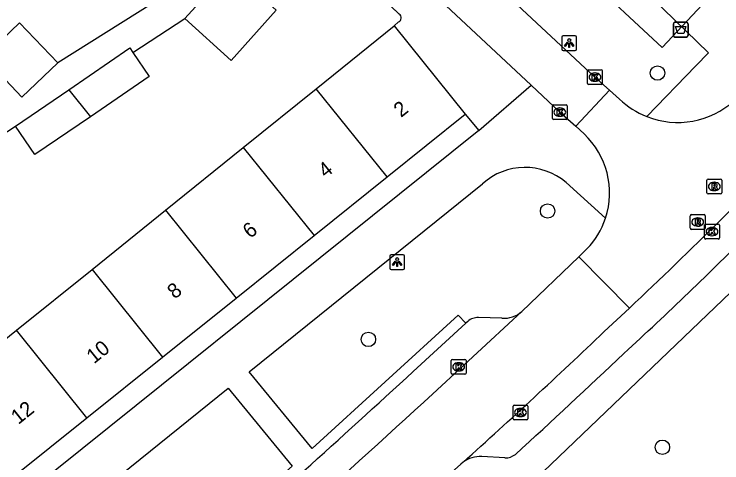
# Model space of a CAD drawing. Extents: x 162347 to 162868, y 381221 to 381813.
# Drawn here: x 162598.22 to 162646.11, y 381599.97 to 381630.34 of the extents above; entities that cross this region are included whole.
import ezdxf

# ---------------------------------------------------------------- set-up
doc = ezdxf.new("R2010")
doc.units = 0
for name, color, linetype in [('IMGEO_Afvalbak', 7, 'Continuous'), ('IMGEO_Boom', 7, 'Continuous'), ('IMGEO_Hek', 7, 'Continuous'), ('IMGEO_Kolk', 7, 'Continuous'), ('IMGEO_Lichtpunt', 7, 'Continuous'), ('IMGEO_Muur', 7, 'Continuous'), ('IMGEO_Pand', 7, 'Continuous'), ('IMGEO_Pand_nummerreeks', 7, 'Continuous'), ('IMGEO_Parkeervlak_open', 7, 'Continuous'), ('IMGEO_Rijbaan_lokaal_open', 7, 'Continuous'), ('IMGEO_Rioolput', 7, 'Continuous'), ('IMGEO_Voetpad_open', 7, 'Continuous')]:
    doc.layers.add(name, color=color, linetype=linetype)

msp = doc.modelspace()

# ---------------------------------------------------------------- linework, layer by layer
at = {"layer": 'IMGEO_Afvalbak'}
for p, q in [((162642.832, 381628.889), (162642.832, 381629.689)), ((162642.832, 381629.689), (162642.832, 381628.889)), ((162642.932, 381629.789), (162643.722, 381629.789)), ((162643.722, 381629.789), (162642.932, 381629.789)), ((162643.822, 381629.689), (162643.822, 381628.889)), ((162643.822, 381628.889), (162643.822, 381629.689)), ((162643.722, 381628.789), (162642.932, 381628.789)), ((162642.932, 381628.789), (162643.722, 381628.789))]:
    msp.add_line(p, q, dxfattribs=at)
msp.add_lwpolyline([(162642.975, 381629.503), (162643.679, 381629.503), (162643.53, 381629.033), (162643.124, 381629.033), (162642.975, 381629.503)], dxfattribs=at)
for centre, start, end in [((162642.932, 381629.689), 90, 180), ((162642.932, 381629.689), 90, 180), ((162643.722, 381629.689), 0, 90), ((162643.722, 381629.689), 360, 90), ((162642.932, 381628.889), 180, 270), ((162642.932, 381628.889), 180, 270), ((162643.722, 381628.889), 270, 0), ((162643.722, 381628.889), 270, 0)]:
    msp.add_arc(centre, 0.1, start, end, dxfattribs=at)
at = {"layer": 'IMGEO_Boom'}
for centre in [(162641.754, 381626.354), (162634.319, 381617.015), (162622.19, 381608.325), (162642.088, 381601.02)]:
    msp.add_circle(centre, 0.489, dxfattribs=at)
at = {"layer": 'IMGEO_Hek'}
msp.add_lwpolyline([(162652.232, 381638.954), (162642.062, 381628.072), (162636.69, 381633.102)], dxfattribs=at)
at = {"layer": 'IMGEO_Kolk'}
for p, q in [((162637.021, 381625.651), (162637.021, 381626.503)), ((162637.096, 381626.577), (162637.948, 381626.577)), ((162637.509, 381626.357), (162637.534, 381626.357)), ((162638.022, 381626.503), (162638.022, 381625.651)), ((162637.532, 381625.797), (162637.507, 381625.797)), ((162637.948, 381625.577), (162637.096, 381625.577)), ((162634.644, 381623.282), (162634.644, 381624.134)), ((162634.719, 381624.208), (162635.571, 381624.208)), ((162635.132, 381623.988), (162635.157, 381623.988)), ((162635.645, 381624.134), (162635.645, 381623.282)), ((162635.155, 381623.428), (162635.13, 381623.428)), ((162635.571, 381623.208), (162634.719, 381623.208)), ((162645.016, 381616.12), (162645.868, 381616.12)), ((162644.941, 381615.194), (162644.941, 381616.046)), ((162645.429, 381615.9), (162645.454, 381615.9)), ((162645.942, 381616.046), (162645.942, 381615.194)), ((162645.452, 381615.34), (162645.427, 381615.34)), ((162645.868, 381615.12), (162645.016, 381615.12)), ((162627.802, 381606.041), (162627.802, 381606.893)), ((162627.877, 381606.967), (162628.729, 381606.967)), ((162628.29, 381606.747), (162628.315, 381606.747)), ((162628.803, 381606.893), (162628.803, 381606.041)), ((162628.313, 381606.187), (162628.288, 381606.187)), ((162628.729, 381605.967), (162627.877, 381605.967)), ((162631.982, 381602.949), (162631.982, 381603.801)), ((162632.057, 381603.875), (162632.909, 381603.875)), ((162632.47, 381603.655), (162632.495, 381603.655)), ((162632.983, 381603.801), (162632.983, 381602.949)), ((162632.909, 381602.875), (162632.057, 381602.875)), ((162632.493, 381603.095), (162632.468, 381603.095))]:
    msp.add_line(p, q, dxfattribs=at)
for points in [[(162637.021, 381625.651), (162637.021, 381626.503)], [(162637.096, 381626.577), (162637.948, 381626.577)], [(162637.342, 381626.277), (162637.465, 381626.277), (162637.465, 381626.126), (162637.595, 381626.277), (162637.759, 381626.277), (162637.613, 381626.126), (162637.766, 381625.877), (162637.614, 381625.877), (162637.529, 381626.041), (162637.465, 381625.974), (162637.465, 381625.877), (162637.342, 381625.877), (162637.342, 381626.277)], [(162638.022, 381626.503), (162638.022, 381625.651)], [(162637.948, 381625.577), (162637.096, 381625.577)], [(162634.644, 381623.282), (162634.644, 381624.134)], [(162634.719, 381624.208), (162635.571, 381624.208)], [(162634.965, 381623.908), (162635.088, 381623.908), (162635.088, 381623.757), (162635.218, 381623.908), (162635.382, 381623.908), (162635.236, 381623.757), (162635.389, 381623.508), (162635.237, 381623.508), (162635.152, 381623.672), (162635.088, 381623.605), (162635.088, 381623.508), (162634.965, 381623.508), (162634.965, 381623.908)], [(162635.645, 381624.134), (162635.645, 381623.282)], [(162635.571, 381623.208), (162634.719, 381623.208)], [(162645.016, 381616.12), (162645.868, 381616.12)], [(162644.941, 381615.194), (162644.941, 381616.046)], [(162645.262, 381615.82), (162645.385, 381615.82), (162645.385, 381615.669), (162645.515, 381615.82), (162645.679, 381615.82), (162645.533, 381615.669), (162645.686, 381615.42), (162645.534, 381615.42), (162645.449, 381615.584), (162645.385, 381615.517), (162645.385, 381615.42), (162645.262, 381615.42), (162645.262, 381615.82)], [(162645.942, 381616.046), (162645.942, 381615.194)], [(162645.868, 381615.12), (162645.016, 381615.12)], [(162627.802, 381606.041), (162627.802, 381606.893)], [(162627.877, 381606.967), (162628.729, 381606.967)], [(162628.123, 381606.667), (162628.246, 381606.667), (162628.246, 381606.516), (162628.376, 381606.667), (162628.54, 381606.667), (162628.394, 381606.516), (162628.547, 381606.267), (162628.395, 381606.267), (162628.31, 381606.431), (162628.246, 381606.364), (162628.246, 381606.267), (162628.123, 381606.267), (162628.123, 381606.667)], [(162628.803, 381606.893), (162628.803, 381606.041)], [(162628.729, 381605.967), (162627.877, 381605.967)], [(162631.982, 381602.949), (162631.982, 381603.801)], [(162632.057, 381603.875), (162632.909, 381603.875)], [(162632.983, 381603.801), (162632.983, 381602.949)], [(162632.303, 381603.575), (162632.426, 381603.575), (162632.426, 381603.424), (162632.556, 381603.575), (162632.72, 381603.575), (162632.574, 381603.424), (162632.727, 381603.175), (162632.575, 381603.175), (162632.49, 381603.339), (162632.426, 381603.272), (162632.426, 381603.175), (162632.303, 381603.175), (162632.303, 381603.575)], [(162632.909, 381602.875), (162632.057, 381602.875)]]:
    msp.add_lwpolyline(points, dxfattribs=at)
for centre, start, end in [((162637.098, 381626.501), 91.552, 178.448), ((162637.098, 381626.501), 91.552, 178.448), ((162637.946, 381626.501), 1.552, 88.448), ((162637.946, 381626.501), 1.552, 88.448), ((162637.098, 381625.653), 181.552, 268.448), ((162637.098, 381625.653), 181.552, 268.448), ((162637.946, 381625.653), 271.552, 358.448), ((162637.946, 381625.653), 271.552, 358.448), ((162634.721, 381624.132), 91.552, 178.448), ((162634.721, 381624.132), 91.552, 178.448), ((162635.569, 381624.132), 1.552, 88.448), ((162635.569, 381624.132), 1.552, 88.448), ((162634.721, 381623.284), 181.552, 268.448), ((162634.721, 381623.284), 181.552, 268.448), ((162635.569, 381623.284), 271.552, 358.448), ((162635.569, 381623.284), 271.552, 358.448), ((162645.018, 381616.044), 91.552, 178.448), ((162645.018, 381616.044), 91.552, 178.448), ((162645.866, 381616.044), 1.552, 88.448), ((162645.866, 381616.044), 1.552, 88.448), ((162645.018, 381615.196), 181.552, 268.448), ((162645.018, 381615.196), 181.552, 268.448), ((162645.866, 381615.196), 271.552, 358.448), ((162645.866, 381615.196), 271.552, 358.448), ((162627.879, 381606.891), 91.552, 178.448), ((162627.879, 381606.891), 91.552, 178.448), ((162628.727, 381606.891), 1.552, 88.448), ((162628.727, 381606.891), 1.552, 88.448), ((162627.879, 381606.043), 181.552, 268.448), ((162627.879, 381606.043), 181.552, 268.448), ((162628.727, 381606.043), 271.552, 358.448), ((162628.727, 381606.043), 271.552, 358.448), ((162632.059, 381603.799), 91.552, 178.448), ((162632.059, 381603.799), 91.552, 178.448), ((162632.907, 381603.799), 1.552, 88.448), ((162632.907, 381603.799), 1.552, 88.448), ((162632.059, 381602.951), 181.552, 268.448), ((162632.059, 381602.951), 181.552, 268.448), ((162632.907, 381602.951), 271.552, 358.448), ((162632.907, 381602.951), 271.552, 358.448)]:
    msp.add_arc(centre, 0.0765, start, end, dxfattribs=at)
for centre, major_axis, ratio, start_param, end_param in [((162637.508, 381626.077), (-0.387, 0.002), 0.722429, 4.712389, 7.853982), ((162637.533, 381626.077), (-0.39, 0.002), 0.717154, 1.570796, 4.712389), ((162635.131, 381623.708), (-0.387, 0.002), 0.722429, 4.712389, 7.853982), ((162635.156, 381623.708), (-0.39, 0.002), 0.717154, 1.570796, 4.712389), ((162645.428, 381615.62), (-0.387, 0.002), 0.722429, 4.712389, 7.853982), ((162645.453, 381615.62), (-0.39, 0.002), 0.717154, 1.570796, 4.712389), ((162628.289, 381606.467), (-0.387, 0.002), 0.722429, 4.712389, 7.853982), ((162628.314, 381606.467), (-0.39, 0.002), 0.717154, 1.570796, 4.712389), ((162632.469, 381603.375), (-0.387, 0.002), 0.722429, 4.712389, 7.853982), ((162632.494, 381603.375), (-0.39, 0.002), 0.717154, 1.570796, 4.712389)]:
    msp.add_ellipse(centre, major_axis=major_axis, ratio=ratio, start_param=start_param, end_param=end_param, dxfattribs=at)
at = {"layer": 'IMGEO_Lichtpunt'}
for p, q in [((162635.284, 381628.785), (162635.284, 381627.978)), ((162635.284, 381628.785), (162635.284, 381627.978)), ((162636.186, 381628.88), (162635.378, 381628.88)), ((162636.186, 381628.88), (162635.378, 381628.88)), ((162636.28, 381627.978), (162636.28, 381628.785)), ((162636.28, 381627.978), (162636.28, 381628.785)), ((162635.378, 381627.884), (162636.186, 381627.884)), ((162635.378, 381627.884), (162636.186, 381627.884)), ((162623.639, 381613.96), (162623.639, 381613.153)), ((162623.639, 381613.96), (162623.639, 381613.153)), ((162624.541, 381614.055), (162623.733, 381614.055)), ((162624.541, 381614.055), (162623.733, 381614.055)), ((162624.635, 381613.153), (162624.635, 381613.96)), ((162624.635, 381613.153), (162624.635, 381613.96)), ((162623.733, 381613.059), (162624.541, 381613.059)), ((162623.733, 381613.059), (162624.541, 381613.059))]:
    msp.add_line(p, q, dxfattribs=at)
for points in [[(162635.658, 381628.449), (162635.697, 381628.421), (162635.509, 381628.159), (162635.471, 381628.186), (162635.658, 381628.449)], [(162635.76, 381628.401), (162635.807, 381628.401), (162635.807, 381628.079), (162635.76, 381628.079), (162635.76, 381628.401)], [(162635.87, 381628.421), (162635.908, 381628.448), (162636.095, 381628.186), (162636.056, 381628.158), (162635.87, 381628.421)], [(162624.013, 381613.624), (162624.052, 381613.596), (162623.864, 381613.334), (162623.826, 381613.361), (162624.013, 381613.624)], [(162624.115, 381613.576), (162624.162, 381613.576), (162624.162, 381613.254), (162624.115, 381613.254), (162624.115, 381613.576)], [(162624.225, 381613.596), (162624.263, 381613.623), (162624.45, 381613.361), (162624.411, 381613.333), (162624.225, 381613.596)]]:
    msp.add_lwpolyline(points, dxfattribs=at)
for centre in [(162635.783, 381628.583), (162624.138, 381613.758)]:
    msp.add_circle(centre, 0.0994, dxfattribs=at)
for centre, start, end in [((162635.378, 381628.785), 90, 180), ((162635.378, 381628.785), 90, 180), ((162636.186, 381628.785), 0, 90), ((162636.186, 381628.785), 0, 90), ((162635.378, 381627.978), 180, 270), ((162635.378, 381627.978), 180, 270), ((162636.186, 381627.978), 270, 0), ((162636.186, 381627.978), 270, 360), ((162623.733, 381613.96), 90, 180), ((162623.733, 381613.96), 90, 180), ((162624.541, 381613.96), 0, 90), ((162624.541, 381613.96), 0, 90), ((162623.733, 381613.153), 180, 270), ((162623.733, 381613.153), 180, 270), ((162624.541, 381613.153), 270, 0), ((162624.541, 381613.153), 270, 360)]:
    msp.add_arc(centre, 0.0946, start, end, dxfattribs=at)
at = {"layer": 'IMGEO_Muur'}
for points in [[(162618.878, 381635.534), (162624.28, 381630.339)], [(162623.946, 381629.551), (162624.231, 381629.81)]]:
    msp.add_lwpolyline(points, dxfattribs=at)
msp.add_arc((162624.112, 381630.088), 0.302, 293.1661, 56.2498, dxfattribs=at)
at = {"layer": 'IMGEO_Pand'}
for points in [[(162609.777, 381630.035), (162612.88, 381633.472)], [(162615.058, 381631.44), (162615.96, 381630.598), (162612.904, 381627.212), (162609.777, 381630.035)], [(162596.194, 381627.482), (162598.582, 381629.76), (162601.177, 381627.038)], [(162618.667, 381625.295), (162623.946, 381629.551)], [(162623.946, 381629.551), (162628.75, 381623.566)], [(162601.916, 381625.226), (162606.053, 381628.052), (162606.262, 381627.745)], [(162606.262, 381627.745), (162607.37, 381626.124), (162603.382, 381623.399)], [(162601.177, 381627.038), (162598.75, 381624.723), (162596.155, 381627.445), (162596.194, 381627.482)], [(162598.316, 381622.766), (162601.916, 381625.226)], [(162601.916, 381625.226), (162603.382, 381623.399)], [(162613.728, 381621.312), (162618.667, 381625.295)], [(162623.462, 381619.322), (162618.667, 381625.295)], [(162603.382, 381623.399), (162599.633, 381620.838), (162598.316, 381622.766)], [(162623.462, 381619.322), (162628.75, 381623.566)], [(162608.464, 381617.068), (162613.728, 381621.312)], [(162613.728, 381621.312), (162618.513, 381615.351)], [(162618.513, 381615.351), (162623.462, 381619.322)], [(162603.495, 381613.061), (162608.464, 381617.068)], [(162608.464, 381617.068), (162613.24, 381611.118)], [(162613.24, 381611.118), (162618.513, 381615.351)], [(162598.393, 381608.947), (162603.495, 381613.061)], [(162603.495, 381613.061), (162608.261, 381607.123)], [(162608.261, 381607.123), (162613.24, 381611.118)], [(162593.384, 381604.909), (162598.393, 381608.947)], [(162603.15, 381603.02), (162598.393, 381608.947)], [(162603.15, 381603.02), (162608.261, 381607.123)], [(162598.133, 381598.994), (162603.15, 381603.02)]]:
    msp.add_lwpolyline(points, dxfattribs=at)
at = {"layer": 'IMGEO_Parkeervlak_open'}
for points in [[(162628.918, 381609.544), (162628.789, 381609.425)], [(162631.231, 381609.754), (162629.635, 381609.796)]]:
    msp.add_lwpolyline(points, dxfattribs=at)
for centre, radius, start, end in [((162631.345, 381611.623), 1.873, 266.5245, 310.9088), ((162629.57, 381608.834), 0.964, 86.1469, 132.5826)]:
    msp.add_arc(centre, radius, start, end, dxfattribs=at)
at = {"layer": 'IMGEO_Rijbaan_lokaal_open'}
for points in [[(162633.2, 381625.535), (162626.089, 381632.217), (162624.566, 381633.613), (162621.502, 381636.51)], [(162638.503, 381625.198), (162637.522, 381626.077), (162632.252, 381630.976)], [(162633.2, 381625.535), (162635.145, 381623.708), (162636.238, 381622.763)], [(162636.238, 381622.763), (162638.503, 381625.198)], [(162638.503, 381625.198), (162639.185, 381624.588)], [(162636.787, 381622.23), (162636.238, 381622.763)], [(162646.045, 381616.42), (162650.694, 381621.134)], [(162636.433, 381613.917), (162636.982, 381614.446)], [(162632.571, 381610.208), (162636.433, 381613.917)], [(162636.433, 381613.917), (162639.859, 381610.448)], [(162639.859, 381610.448), (162638.153, 381608.851)], [(162625.936, 381604.079), (162632.571, 381610.208)], [(162628.605, 381600.016), (162628.438, 381599.881), (162626.535, 381598.164)]]:
    msp.add_lwpolyline(points, dxfattribs=at)
for centre, radius, start, end in [((162643.143, 381628.73), 5.729, 226.3053, 248.3061), ((162643.12, 381628.699), 5.691, 248.4036, 312.3099), ((162633.039, 381618.241), 5.474, 341.7014, 46.7864), ((162633.069, 381618.226), 5.441, 315.9882, 341.7439), ((162394.841, 381870.436), 357.25, 313.30209, 314.68113), ((162327.045, 381935.489), 451.088, 311.95267, 313.60503), ((161942.339, 382348.939), 1011, 311.016557, 312.544247)]:
    msp.add_arc(centre, radius, start, end, dxfattribs=at)
at = {"layer": 'IMGEO_Rioolput'}
for p, q in [((162645.097, 381618.25), (162645.097, 381619.102)), ((162645.172, 381619.176), (162646.024, 381619.176)), ((162646.098, 381619.102), (162646.098, 381618.25)), ((162645.585, 381618.956), (162645.61, 381618.956)), ((162646.024, 381618.176), (162645.172, 381618.176)), ((162645.608, 381618.396), (162645.583, 381618.396)), ((162643.976, 381615.844), (162643.976, 381616.696)), ((162644.051, 381616.77), (162644.903, 381616.77)), ((162644.977, 381616.696), (162644.977, 381615.844)), ((162644.464, 381616.55), (162644.489, 381616.55)), ((162644.903, 381615.77), (162644.051, 381615.77)), ((162644.487, 381615.99), (162644.462, 381615.99))]:
    msp.add_line(p, q, dxfattribs=at)
for points in [[(162645.097, 381618.25), (162645.097, 381619.102)], [(162645.172, 381619.176), (162646.024, 381619.176)], [(162646.098, 381619.102), (162646.098, 381618.25)], [(162645.686, 381618.874), (162645.434, 381618.876), (162645.434, 381618.476)], [(162645.434, 381618.476), (162645.558, 381618.476), (162645.558, 381618.638), (162645.569, 381618.638)], [(162645.612, 381618.795), (162645.558, 381618.795), (162645.558, 381618.714)], [(162645.558, 381618.714), (162645.61, 381618.714)], [(162645.616, 381618.609), (162645.687, 381618.476), (162645.827, 381618.476), (162645.762, 381618.602)], [(162646.024, 381618.176), (162645.172, 381618.176)], [(162643.976, 381615.844), (162643.976, 381616.696)], [(162644.051, 381616.77), (162644.903, 381616.77)], [(162644.977, 381616.696), (162644.977, 381615.844)], [(162644.565, 381616.468), (162644.313, 381616.47), (162644.313, 381616.07)], [(162644.313, 381616.07), (162644.437, 381616.07), (162644.437, 381616.232), (162644.448, 381616.232)], [(162644.491, 381616.389), (162644.437, 381616.389), (162644.437, 381616.308)], [(162644.437, 381616.308), (162644.489, 381616.308)], [(162644.495, 381616.203), (162644.566, 381616.07), (162644.706, 381616.07), (162644.641, 381616.196)], [(162644.903, 381615.77), (162644.051, 381615.77)]]:
    msp.add_lwpolyline(points, dxfattribs=at)
for centre, radius, start, end in [((162645.174, 381619.1), 0.0765, 91.552, 178.448), ((162645.174, 381619.1), 0.0765, 91.552, 178.448), ((162646.022, 381619.1), 0.0765, 1.552, 88.448), ((162646.022, 381619.1), 0.0765, 1.552, 88.448), ((162645.568, 381618.585), 0.0533, 26.0293, 88.6989), ((162645.594, 381618.903), 0.19, 274.7715, 282.9687), ((162645.618, 381618.699), 0.0964, 77.0061, 93.1865), ((162645.632, 381618.756), 0.0378, 276.6634, 79.6772), ((162645.685, 381618.764), 0.109, 350.3612, 89.416), ((162645.683, 381618.764), 0.112, 277.5842, 350.9817), ((162645.667, 381618.549), 0.108, 29.5134, 73.7905), ((162645.174, 381618.252), 0.0765, 181.552, 268.448), ((162645.174, 381618.252), 0.0765, 181.552, 268.448), ((162646.022, 381618.252), 0.0765, 271.552, 358.448), ((162646.022, 381618.252), 0.0765, 271.552, 358.448), ((162644.053, 381616.694), 0.0765, 91.552, 178.448), ((162644.053, 381616.694), 0.0765, 91.552, 178.448), ((162644.901, 381616.694), 0.0765, 1.552, 88.448), ((162644.901, 381616.694), 0.0765, 1.552, 88.448), ((162644.447, 381616.179), 0.0533, 26.0293, 88.6989), ((162644.473, 381616.497), 0.19, 274.7715, 282.9687), ((162644.497, 381616.293), 0.0964, 77.0061, 93.1865), ((162644.511, 381616.35), 0.0378, 276.6634, 79.6772), ((162644.564, 381616.358), 0.109, 350.3612, 89.416), ((162644.562, 381616.358), 0.112, 277.5842, 350.9817), ((162644.546, 381616.143), 0.108, 29.5134, 73.7905), ((162644.053, 381615.846), 0.0765, 181.552, 268.448), ((162644.053, 381615.846), 0.0765, 181.552, 268.448), ((162644.901, 381615.846), 0.0765, 271.552, 358.448), ((162644.901, 381615.846), 0.0765, 271.552, 358.448)]:
    msp.add_arc(centre, radius, start, end, dxfattribs=at)
for centre, major_axis, ratio, start_param, end_param in [((162645.584, 381618.676), (-0.387, 0.002), 0.722429, 4.712389, 7.853982), ((162645.609, 381618.676), (-0.39, 0.002), 0.717154, 1.570796, 4.712389), ((162644.463, 381616.27), (-0.387, 0.002), 0.722429, 4.712389, 7.853982), ((162644.488, 381616.27), (-0.39, 0.002), 0.717154, 1.570796, 4.712389)]:
    msp.add_ellipse(centre, major_axis=major_axis, ratio=ratio, start_param=start_param, end_param=end_param, dxfattribs=at)
at = {"layer": 'IMGEO_Voetpad_open'}
for points in [[(162624.28, 381630.339), (162618.835, 381635.59)], [(162637.524, 381635.211), (162645.202, 381627.721), (162644.357, 381626.848), (162641.025, 381623.407)], [(162609.836, 381632.495), (162601.177, 381627.038)], [(162606.262, 381627.745), (162609.777, 381630.035)], [(162623.946, 381629.551), (162624.231, 381629.81)], [(162629.662, 381622.463), (162633.2, 381625.535)], [(162628.75, 381623.566), (162629.662, 381622.463)], [(162588.949, 381616.664), (162598.316, 381622.766)], [(162629.662, 381622.463), (162593.892, 381593.755)], [(162628.789, 381609.425), (162628.272, 381609.975), (162618.384, 381600.939), (162614.116, 381606.124), (162629.916, 381618.858)], [(162635.574, 381618.945), (162638.236, 381616.522)], [(162630.312, 381595.808), (162647.237, 381612.021)], [(162625.222, 381606.148), (162628.789, 381609.425)], [(162596.806, 381592.212), (162612.702, 381605.014), (162617.041, 381599.75), (162606.244, 381590.2), (162606.748, 381589.646)], [(162631.429, 381600.301), (162629.862, 381600.388)]]:
    msp.add_lwpolyline(points, dxfattribs=at)
for centre, radius, start, end in [((162624.112, 381630.088), 0.302, 293.1661, 56.2498), ((162632.795, 381615.668), 4.297, 49.6956, 132.0663), ((162453.187, 381810.05), 275.288, 312.58981, 315.08241), ((162193.579, 382078.628), 648.775, 312.530546, 313.417235), ((162012.532, 382272.566), 905.263, 311.328974, 312.594769), ((162629.761, 381598.421), 1.97, 87.0532, 125.9183), ((162631.419, 381601.533), 1.232, 270.4636, 305.8252)]:
    msp.add_arc(centre, radius, start, end, dxfattribs=at)

# ---------------------------------------------------------------- texts
at = {"layer": 'IMGEO_Pand_nummerreeks'}
for s, p in [('2', (162624.403, 381623.308)), ('4', (162619.298, 381619.212)), ('6', (162614.191, 381615.114)), ('8', (162609.087, 381611.017)), ('10', (162603.622, 381606.63)), ('12', (162598.51, 381602.527))]:
    msp.add_text(s, height=1, rotation=38.749, dxfattribs=at).set_placement(p)

doc.saveas('drawing.dxf')
